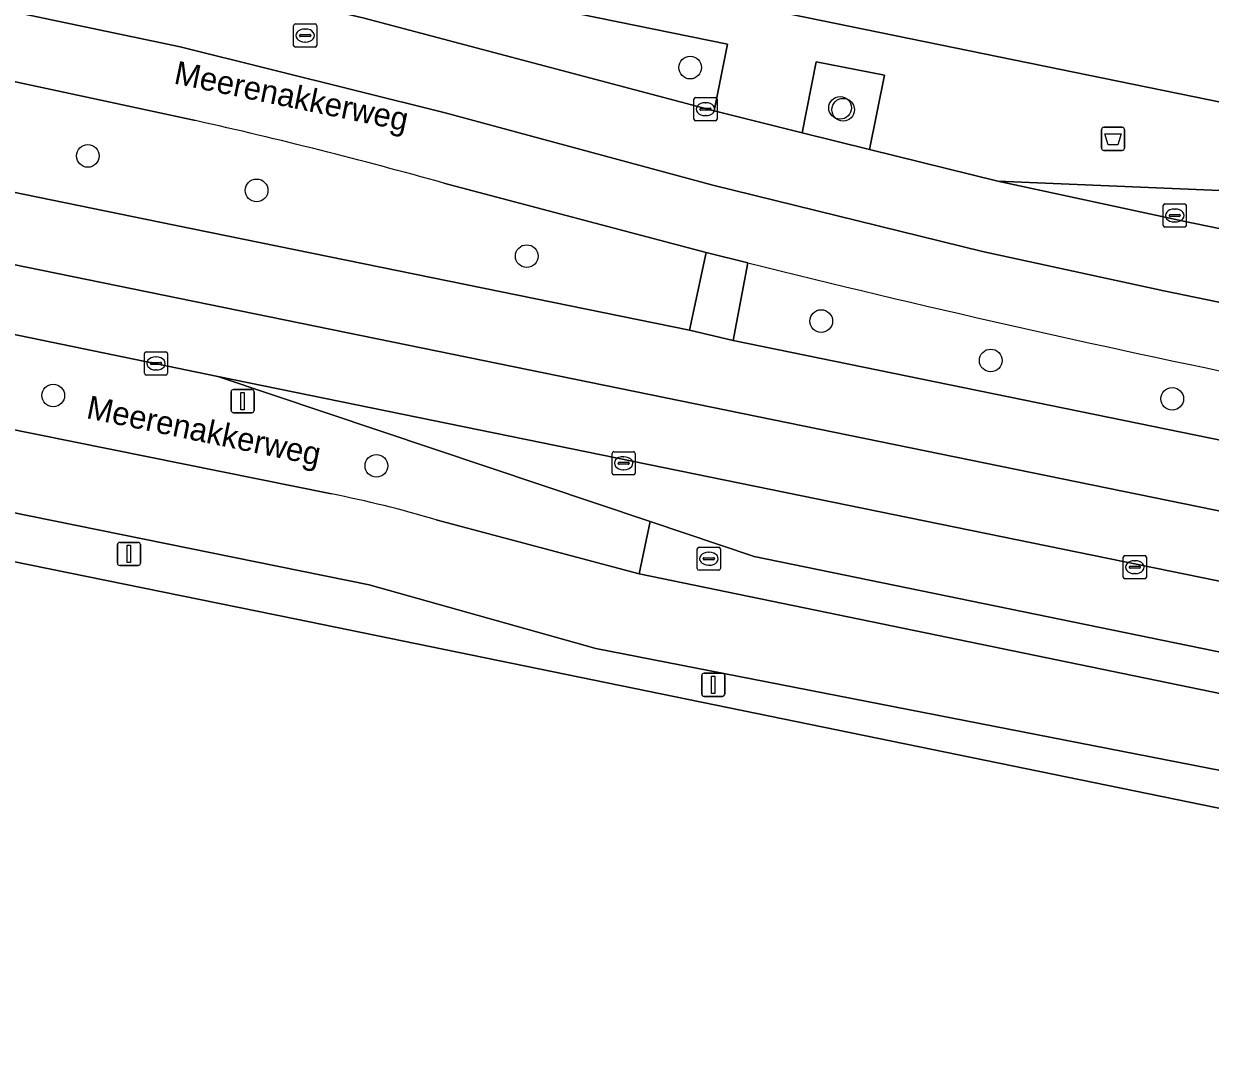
# Model space of a CAD drawing. Extents: x 157692 to 159674, y 381452 to 383291.
# Drawn here: x 158207.7 to 158258.9, y 382136.5 to 382181.5 of the extents above; entities that cross this region are included whole.
import ezdxf

# ---------------------------------------------------------------- set-up
doc = ezdxf.new("R2010")
doc.units = 0
for name, color, linetype in [('IMGEO_Afvalbak', 7, 'Continuous'), ('IMGEO_Berm_groen', 7, 'Continuous'), ('IMGEO_Boom', 7, 'Continuous'), ('IMGEO_Erf', 7, 'Continuous'), ('IMGEO_Fietspad_gesloten', 7, 'Continuous'), ('IMGEO_Kolk', 7, 'Continuous'), ('IMGEO_Lichtmast', 7, 'Continuous'), ('IMGEO_Openbare_ruimte_label', 7, 'Continuous'), ('IMGEO_Rijbaan_lokaal_gesloten', 7, 'Continuous'), ('IMGEO_Rijbaan_regionaal_gesloten', 7, 'Continuous'), ('IMGEO_Rioolput', 7, 'Continuous'), ('IMGEO_Verkeerseiland_groen', 7, 'Continuous'), ('IMGEO_Voetpad_open', 7, 'Continuous')]:
    doc.layers.add(name, color=color, linetype=linetype)

msp = doc.modelspace()

# ---------------------------------------------------------------- linework, layer by layer
at = {"layer": 'IMGEO_Afvalbak'}
for p, q in [((158254.235, 382176.162), (158254.235, 382176.962)), ((158254.235, 382176.962), (158254.235, 382176.162)), ((158254.335, 382177.062), (158255.125, 382177.062)), ((158255.125, 382177.062), (158254.335, 382177.062)), ((158255.225, 382176.962), (158255.225, 382176.162)), ((158255.225, 382176.162), (158255.225, 382176.962)), ((158255.125, 382176.062), (158254.335, 382176.062)), ((158254.335, 382176.062), (158255.125, 382176.062))]:
    msp.add_line(p, q, dxfattribs=at)
msp.add_lwpolyline([(158254.378, 382176.776), (158255.082, 382176.776), (158254.933, 382176.306), (158254.527, 382176.306), (158254.378, 382176.776)], dxfattribs=at)
for centre, start, end in [((158254.335, 382176.962), 90, 180), ((158254.335, 382176.962), 90, 180), ((158255.125, 382176.962), 0, 90), ((158255.125, 382176.962), 360, 90), ((158254.335, 382176.162), 180, 270), ((158254.335, 382176.162), 180, 270), ((158255.125, 382176.162), 270, 0), ((158255.125, 382176.162), 270, 0)]:
    msp.add_arc(centre, 0.1, start, end, dxfattribs=at)
at = {"layer": 'IMGEO_Berm_groen'}
msp.add_lwpolyline([(158217.378, 382184.889), (158216.981, 382183.063), (158222.394, 382181.778), (158237.511, 382177.767), (158238.086, 382180.651)], close=True, dxfattribs=at)
for points in [[(158215.125, 382177.352), (158206.323, 382179.235), (158205.35, 382174.654), (158214.208, 382172.83), (158236.448, 382168.3), (158237.16, 382171.658), (158225.845, 382174.652)], [(158238.963, 382171.216), (158238.332, 382167.86), (158332.654, 382148.555), (158337.281, 382147.627)], [(158216.08, 382166.299), (158204.843, 382168.616), (158202.239, 382166.987), (158201.858, 382165.089), (158220.985, 382161.23)], [(158225.504, 382160.111), (158234.272, 382157.776), (158234.755, 382160.038), (158216.08, 382166.299)]]:
    msp.add_lwpolyline(points, dxfattribs=at)
for centre, radius, start, end in [((158168.564, 381969.857), 212.654, 74.37377, 77.35262), ((158363, 382666.095), 510.187, 255.92925, 258.52743), ((158211.851, 382114.657), 47.46, 73.2808, 78.9034)]:
    msp.add_arc(centre, radius, start, end, dxfattribs=at)
at = {"layer": 'IMGEO_Boom'}
for centre in [(158236.473, 382179.64), (158242.947, 382177.899), (158243.08, 382177.822), (158210.471, 382175.825), (158217.757, 382174.339), (158229.417, 382171.5), (158242.135, 382168.695), (158249.451, 382166.995), (158208.977, 382165.478), (158257.29, 382165.334), (158222.926, 382162.444)]:
    msp.add_circle(centre, 0.489, dxfattribs=at)
at = {"layer": 'IMGEO_Erf'}
for points in [[(158244.45, 382340.754), (158240.4, 382321.2), (158235.573, 382297.761), (158234.161, 382290.853), (158229.78, 382269.461), (158225.787, 382250), (158225.725, 382249.696), (158216.641, 382204.803), (158214.109, 382192.305), (158213.748, 382190.526), (158214.442, 382188.118), (158215.74, 382187.088), (158329.552, 382163.801), (158340.615, 382161.542)], [(158482.902, 382100.939), (158451.557, 382108.262), (158420.864, 382114.543), (158420.794, 382114.557), (158413.202, 382116.111), (158407.519, 382117.274), (158341.43, 382130.834), (158335.43, 382132.061), (158334.656, 382132.219), (158219.414, 382155.844), (158206.316, 382158.502)]]:
    msp.add_lwpolyline(points, dxfattribs=at)
at = {"layer": 'IMGEO_Fietspad_gesloten'}
for points in [[(158220.985, 382161.23), (158201.858, 382165.089), (158188.611, 382167.78), (158162.259, 382173.124)], [(158159.005, 382170.201), (158187.438, 382164.416), (158201.188, 382161.648), (158222.611, 382157.3), (158232.397, 382154.551), (158296.287, 382142.071), (158300.227, 382141.376), (158311.012, 382139.189), (158315.925, 382138.175), (158316.6, 382141.413)], [(158316.6, 382141.413), (158316.605, 382141.634), (158311.936, 382142.594), (158297.48, 382145.479), (158277.512, 382148.874), (158234.272, 382157.776), (158225.504, 382160.111)]]:
    msp.add_lwpolyline(points, dxfattribs=at)
msp.add_arc((158211.851, 382114.657), 47.46, 73.2808, 78.9034, dxfattribs=at)
at = {"layer": 'IMGEO_Kolk'}
for p, q in [((158236.637, 382177.418), (158236.637, 382178.27)), ((158236.712, 382178.344), (158237.564, 382178.344)), ((158237.125, 382178.124), (158237.15, 382178.124)), ((158237.638, 382178.27), (158237.638, 382177.418)), ((158236.896, 382177.838), (158236.896, 382177.85)), ((158237.334, 382177.801), (158236.936, 382177.801)), ((158236.939, 382177.887), (158237.337, 382177.887)), ((158237.38, 382177.85), (158237.38, 382177.838)), ((158237.564, 382177.344), (158236.712, 382177.344)), ((158237.148, 382177.564), (158237.123, 382177.564)), ((158256.896, 382172.827), (158256.896, 382173.679)), ((158256.971, 382173.753), (158257.823, 382173.753)), ((158257.384, 382173.533), (158257.409, 382173.533)), ((158257.897, 382173.679), (158257.897, 382172.827)), ((158257.155, 382173.247), (158257.155, 382173.259)), ((158257.593, 382173.21), (158257.195, 382173.21)), ((158257.198, 382173.296), (158257.596, 382173.296)), ((158257.639, 382173.259), (158257.639, 382173.247)), ((158257.823, 382172.753), (158256.971, 382172.753)), ((158257.407, 382172.973), (158257.382, 382172.973)), ((158212.987, 382167.365), (158213.839, 382167.365)), ((158212.912, 382166.439), (158212.912, 382167.291)), ((158213.171, 382166.859), (158213.171, 382166.871)), ((158213.214, 382166.908), (158213.612, 382166.908)), ((158213.4, 382167.145), (158213.425, 382167.145)), ((158213.655, 382166.871), (158213.655, 382166.859)), ((158213.913, 382167.291), (158213.913, 382166.439)), ((158213.839, 382166.365), (158212.987, 382166.365)), ((158213.609, 382166.822), (158213.211, 382166.822)), ((158213.423, 382166.585), (158213.398, 382166.585)), ((158233.104, 382162.129), (158233.104, 382162.981)), ((158233.179, 382163.055), (158234.031, 382163.055)), ((158233.592, 382162.835), (158233.617, 382162.835)), ((158234.105, 382162.981), (158234.105, 382162.129)), ((158233.363, 382162.549), (158233.363, 382162.561)), ((158233.801, 382162.512), (158233.403, 382162.512)), ((158233.406, 382162.598), (158233.804, 382162.598)), ((158233.615, 382162.275), (158233.59, 382162.275)), ((158233.847, 382162.561), (158233.847, 382162.549)), ((158234.031, 382162.055), (158233.179, 382162.055)), ((158255.174, 382157.642), (158255.174, 382158.494)), ((158255.249, 382158.568), (158256.101, 382158.568)), ((158255.662, 382158.348), (158255.687, 382158.348)), ((158256.175, 382158.494), (158256.175, 382157.642)), ((158255.433, 382158.062), (158255.433, 382158.074)), ((158255.871, 382158.025), (158255.473, 382158.025)), ((158255.476, 382158.111), (158255.874, 382158.111)), ((158255.685, 382157.788), (158255.66, 382157.788)), ((158255.917, 382158.074), (158255.917, 382158.062)), ((158256.101, 382157.568), (158255.249, 382157.568))]:
    msp.add_line(p, q, dxfattribs=at)
for points in [[(158236.637, 382177.418), (158236.637, 382178.27)], [(158236.712, 382178.344), (158237.564, 382178.344)], [(158237.638, 382178.27), (158237.638, 382177.418)], [(158237.564, 382177.344), (158236.712, 382177.344)], [(158256.896, 382172.827), (158256.896, 382173.679)], [(158256.971, 382173.753), (158257.823, 382173.753)], [(158257.897, 382173.679), (158257.897, 382172.827)], [(158257.823, 382172.753), (158256.971, 382172.753)], [(158212.987, 382167.365), (158213.839, 382167.365)], [(158212.912, 382166.439), (158212.912, 382167.291)], [(158213.913, 382167.291), (158213.913, 382166.439)], [(158213.839, 382166.365), (158212.987, 382166.365)], [(158233.104, 382162.129), (158233.104, 382162.981)], [(158233.179, 382163.055), (158234.031, 382163.055)], [(158234.105, 382162.981), (158234.105, 382162.129)], [(158234.031, 382162.055), (158233.179, 382162.055)], [(158255.174, 382157.642), (158255.174, 382158.494)], [(158255.249, 382158.568), (158256.101, 382158.568)], [(158256.175, 382158.494), (158256.175, 382157.642)], [(158256.101, 382157.568), (158255.249, 382157.568)]]:
    msp.add_lwpolyline(points, dxfattribs=at)
for centre, radius, start, end in [((158236.714, 382178.268), 0.0765, 91.552, 178.448), ((158236.714, 382178.268), 0.0765, 91.552, 178.448), ((158237.562, 382178.268), 0.0765, 1.552, 88.448), ((158237.562, 382178.268), 0.0765, 1.552, 88.448), ((158236.936, 382177.847), 0.0403, 85.8775, 175.7526), ((158236.933, 382177.837), 0.0366, 178.938, 274.7102), ((158237.337, 382177.844), 0.043, 264.8664, 352.4533), ((158237.341, 382177.849), 0.0386, 1.7309, 96.639), ((158236.714, 382177.42), 0.0765, 181.552, 268.448), ((158236.714, 382177.42), 0.0765, 181.552, 268.448), ((158237.562, 382177.42), 0.0765, 271.552, 358.448), ((158237.562, 382177.42), 0.0765, 271.552, 358.448), ((158256.973, 382173.677), 0.0765, 91.552, 178.448), ((158256.973, 382173.677), 0.0765, 91.552, 178.448), ((158257.821, 382173.677), 0.0765, 1.552, 88.448), ((158257.821, 382173.677), 0.0765, 1.552, 88.448), ((158257.195, 382173.256), 0.0403, 85.8775, 175.7526), ((158257.192, 382173.246), 0.0366, 178.938, 274.7102), ((158257.596, 382173.253), 0.043, 264.8664, 352.4533), ((158257.6, 382173.258), 0.0386, 1.7309, 96.639), ((158256.973, 382172.829), 0.0765, 181.552, 268.448), ((158256.973, 382172.829), 0.0765, 181.552, 268.448), ((158257.821, 382172.829), 0.0765, 271.552, 358.448), ((158257.821, 382172.829), 0.0765, 271.552, 358.448), ((158212.989, 382167.289), 0.0765, 91.552, 178.448), ((158212.989, 382167.289), 0.0765, 91.552, 178.448), ((158213.837, 382167.289), 0.0765, 1.552, 88.448), ((158213.837, 382167.289), 0.0765, 1.552, 88.448), ((158213.211, 382166.868), 0.0403, 85.8775, 175.7526), ((158213.208, 382166.858), 0.0366, 178.938, 274.7102), ((158213.612, 382166.865), 0.043, 264.8664, 352.4533), ((158213.616, 382166.87), 0.0386, 1.7309, 96.639), ((158212.989, 382166.441), 0.0765, 181.552, 268.448), ((158212.989, 382166.441), 0.0765, 181.552, 268.448), ((158213.837, 382166.441), 0.0765, 271.552, 358.448), ((158213.837, 382166.441), 0.0765, 271.552, 358.448), ((158233.181, 382162.979), 0.0765, 91.552, 178.448), ((158233.181, 382162.979), 0.0765, 91.552, 178.448), ((158234.029, 382162.979), 0.0765, 1.552, 88.448), ((158234.029, 382162.979), 0.0765, 1.552, 88.448), ((158233.403, 382162.558), 0.0403, 85.8775, 175.7526), ((158233.4, 382162.548), 0.0366, 178.938, 274.7102), ((158233.804, 382162.555), 0.043, 264.8664, 352.4533), ((158233.808, 382162.56), 0.0386, 1.7309, 96.639), ((158233.181, 382162.131), 0.0765, 181.552, 268.448), ((158233.181, 382162.131), 0.0765, 181.552, 268.448), ((158234.029, 382162.131), 0.0765, 271.552, 358.448), ((158234.029, 382162.131), 0.0765, 271.552, 358.448), ((158255.251, 382158.492), 0.0765, 91.552, 178.448), ((158255.251, 382158.492), 0.0765, 91.552, 178.448), ((158256.099, 382158.492), 0.0765, 1.552, 88.448), ((158256.099, 382158.492), 0.0765, 1.552, 88.448), ((158255.251, 382157.644), 0.0765, 181.552, 268.448), ((158255.251, 382157.644), 0.0765, 181.552, 268.448), ((158255.473, 382158.071), 0.0403, 85.8775, 175.7526), ((158255.47, 382158.061), 0.0366, 178.938, 274.7102), ((158255.874, 382158.068), 0.043, 264.8664, 352.4533), ((158255.878, 382158.073), 0.0386, 1.7309, 96.639), ((158256.099, 382157.644), 0.0765, 271.552, 358.448), ((158256.099, 382157.644), 0.0765, 271.552, 358.448)]:
    msp.add_arc(centre, radius, start, end, dxfattribs=at)
for centre, major_axis, ratio, start_param, end_param in [((158237.124, 382177.844), (-0.387, 0.002), 0.722429, 4.712389, 7.853982), ((158237.149, 382177.844), (-0.39, 0.002), 0.717154, 1.570796, 4.712389), ((158257.383, 382173.253), (-0.387, 0.002), 0.722429, 4.712389, 7.853982), ((158257.408, 382173.253), (-0.39, 0.002), 0.717154, 1.570796, 4.712389), ((158213.399, 382166.865), (-0.387, 0.002), 0.722429, 4.712389, 7.853982), ((158213.424, 382166.865), (-0.39, 0.002), 0.717154, 1.570796, 4.712389), ((158233.591, 382162.555), (-0.387, 0.002), 0.722429, 4.712389, 7.853982), ((158233.616, 382162.555), (-0.39, 0.002), 0.717154, 1.570796, 4.712389), ((158255.661, 382158.068), (-0.387, 0.002), 0.722429, 4.712389, 7.853982), ((158255.686, 382158.068), (-0.39, 0.002), 0.717154, 1.570796, 4.712389)]:
    msp.add_ellipse(centre, major_axis=major_axis, ratio=ratio, start_param=start_param, end_param=end_param, dxfattribs=at)
at = {"layer": 'IMGEO_Lichtmast'}
for p, q in [((158216.656, 382164.839), (158216.656, 382165.639)), ((158216.656, 382165.639), (158216.656, 382164.839)), ((158216.756, 382165.739), (158217.546, 382165.739)), ((158217.546, 382165.739), (158216.756, 382165.739)), ((158217.646, 382165.639), (158217.646, 382164.839)), ((158217.646, 382164.839), (158217.646, 382165.639)), ((158217.546, 382164.739), (158216.756, 382164.739)), ((158216.756, 382164.739), (158217.546, 382164.739)), ((158211.748, 382158.24), (158211.748, 382159.04)), ((158211.748, 382159.04), (158211.748, 382158.24)), ((158211.848, 382159.14), (158212.638, 382159.14)), ((158212.638, 382159.14), (158211.848, 382159.14)), ((158212.738, 382159.04), (158212.738, 382158.24)), ((158212.738, 382158.24), (158212.738, 382159.04)), ((158212.638, 382158.14), (158211.848, 382158.14)), ((158211.848, 382158.14), (158212.638, 382158.14)), ((158236.975, 382152.59), (158236.975, 382153.39)), ((158236.975, 382153.39), (158236.975, 382152.59)), ((158237.075, 382153.49), (158237.865, 382153.49)), ((158237.865, 382153.49), (158237.075, 382153.49)), ((158237.965, 382153.39), (158237.965, 382152.59)), ((158237.965, 382152.59), (158237.965, 382153.39)), ((158237.865, 382152.49), (158237.075, 382152.49)), ((158237.075, 382152.49), (158237.865, 382152.49))]:
    msp.add_line(p, q, dxfattribs=at)
for points in [[(158217.076, 382165.614), (158217.226, 382165.614), (158217.226, 382164.864), (158217.076, 382164.864), (158217.076, 382165.614)], [(158212.168, 382159.015), (158212.318, 382159.015), (158212.318, 382158.265), (158212.168, 382158.265), (158212.168, 382159.015)], [(158237.395, 382153.365), (158237.545, 382153.365), (158237.545, 382152.615), (158237.395, 382152.615), (158237.395, 382153.365)]]:
    msp.add_lwpolyline(points, dxfattribs=at)
for centre, start, end in [((158216.756, 382165.639), 90, 180), ((158216.756, 382165.639), 90, 180), ((158217.546, 382165.639), 0, 90), ((158217.546, 382165.639), 360, 90), ((158216.756, 382164.839), 180, 270), ((158216.756, 382164.839), 180, 270), ((158217.546, 382164.839), 270, 0), ((158217.546, 382164.839), 270, 0), ((158211.848, 382159.04), 90, 180), ((158211.848, 382159.04), 90, 180), ((158212.638, 382159.04), 0, 90), ((158212.638, 382159.04), 360, 90), ((158211.848, 382158.24), 180, 270), ((158211.848, 382158.24), 180, 270), ((158212.638, 382158.24), 270, 0), ((158212.638, 382158.24), 270, 0), ((158237.075, 382153.39), 90, 180), ((158237.075, 382153.39), 90, 180), ((158237.865, 382153.39), 0, 90), ((158237.865, 382153.39), 360, 90), ((158237.075, 382152.59), 180, 270), ((158237.075, 382152.59), 180, 270), ((158237.865, 382152.59), 270, 0), ((158237.865, 382152.59), 270, 0)]:
    msp.add_arc(centre, 0.1, start, end, dxfattribs=at)
at = {"layer": 'IMGEO_Rijbaan_lokaal_gesloten'}
for points in [[(158312.633, 382161.717), (158311.966, 382161.947), (158306.509, 382163.787), (158295.909, 382167.348), (158289.33, 382169.533), (158267.837, 382173.953), (158267.219, 382174.004), (158249.756, 382174.73), (158257.777, 382173.009)], [(158234.755, 382160.038), (158239.245, 382158.524), (158260.766, 382154.11), (158278.412, 382153.569), (158216.08, 382166.299)]]:
    msp.add_lwpolyline(points, close=True, dxfattribs=at)
at = {"layer": 'IMGEO_Rijbaan_regionaal_gesloten'}
for points in [[(158261.524, 382166.102), (158275.322, 382163.2), (158286.197, 382161.062), (158295.36, 382159.103), (158314.777, 382155.136), (158321.46, 382153.803), (158323.945, 382153.28), (158334.226, 382151.239), (158339.086, 382150.367), (158341.105, 382150.035), (158343.515, 382152.527), (158327.525, 382155.488), (158318.888, 382157.281), (158300.095, 382161.181), (158268.722, 382167.572), (158256.931, 382169.996), (158249.098, 382171.701), (158237.46, 382174.557), (158225.893, 382177.689), (158214.463, 382180.529), (158188.034, 382186.098), (157930.794, 382238.814)], [(158170.92, 382175.562), (158187.319, 382172.195), (158204.843, 382168.616), (158216.08, 382166.299), (158278.412, 382153.569), (158333.614, 382142.258), (158336.056, 382144.815), (158206.473, 382171.3), (158031.467, 382207.214), (158024.234, 382208.503), (158020.135, 382209.234), (158016.646, 382209.742), (158012.613, 382210.388), (158008.566, 382210.941), (157996.273, 382212.623), (157992.778, 382213.101), (157988.349, 382213.708), (157984.656, 382214.298), (157972.663, 382216.316), (157960.705, 382218.534), (157952.268, 382220.278), (157944.252, 382221.934), (157933.19, 382224.57), (157925.243, 382226.645)], [(158012.828, 382218.933), (158142.514, 382192.31), (158170.978, 382186.516), (158185.711, 382183.483), (158196.081, 382181.334), (158199.217, 382180.702), (158203.207, 382179.878), (158206.323, 382179.235), (158215.125, 382177.352)], [(158188.034, 382186.098), (158214.463, 382180.529), (158225.893, 382177.689), (158237.46, 382174.557), (158249.098, 382171.701), (158256.931, 382169.996), (158268.722, 382167.572), (158300.095, 382161.181), (158318.888, 382157.281), (158327.525, 382155.488), (158343.515, 382152.527), (158346.089, 382155.189), (158341.57, 382155.982), (158334.739, 382157.23), (158325.962, 382159.007), (158312.633, 382161.717), (158257.777, 382173.009), (158249.756, 382174.73), (158244.222, 382176.102), (158241.316, 382176.823), (158237.511, 382177.767), (158222.394, 382181.778), (158216.981, 382183.063), (158188.223, 382189.088)], [(158206.473, 382171.3), (158336.056, 382144.815), (158338.533, 382147.375), (158337.281, 382147.627), (158332.654, 382148.555), (158238.332, 382167.86), (158236.448, 382168.3), (158214.208, 382172.83), (158205.35, 382174.654)], [(158225.845, 382174.652), (158237.16, 382171.658), (158238.963, 382171.216)]]:
    msp.add_lwpolyline(points, dxfattribs=at)
for centre, radius, start, end in [((158168.564, 381969.857), 212.654, 74.37377, 77.35262), ((158363, 382666.095), 510.187, 255.92925, 258.52743)]:
    msp.add_arc(centre, radius, start, end, dxfattribs=at)
at = {"layer": 'IMGEO_Rioolput'}
for p, q in [((158219.355, 382180.597), (158219.355, 382181.449)), ((158219.43, 382181.523), (158220.282, 382181.523)), ((158219.843, 382181.303), (158219.868, 382181.303)), ((158220.356, 382181.449), (158220.356, 382180.597)), ((158219.614, 382181.017), (158219.614, 382181.029)), ((158220.052, 382180.98), (158219.654, 382180.98)), ((158219.657, 382181.066), (158220.055, 382181.066)), ((158219.866, 382180.743), (158219.841, 382180.743)), ((158220.098, 382181.029), (158220.098, 382181.017)), ((158220.282, 382180.523), (158219.43, 382180.523)), ((158236.784, 382158.006), (158236.784, 382158.858)), ((158236.859, 382158.932), (158237.711, 382158.932)), ((158237.272, 382158.712), (158237.297, 382158.712)), ((158237.785, 382158.858), (158237.785, 382158.006)), ((158237.043, 382158.426), (158237.043, 382158.438)), ((158237.481, 382158.389), (158237.083, 382158.389)), ((158237.086, 382158.475), (158237.484, 382158.475)), ((158237.295, 382158.152), (158237.27, 382158.152)), ((158237.527, 382158.438), (158237.527, 382158.426)), ((158237.711, 382157.932), (158236.859, 382157.932))]:
    msp.add_line(p, q, dxfattribs=at)
for points in [[(158219.355, 382180.597), (158219.355, 382181.449)], [(158219.43, 382181.523), (158220.282, 382181.523)], [(158220.356, 382181.449), (158220.356, 382180.597)], [(158220.282, 382180.523), (158219.43, 382180.523)], [(158236.784, 382158.006), (158236.784, 382158.858)], [(158236.859, 382158.932), (158237.711, 382158.932)], [(158237.785, 382158.858), (158237.785, 382158.006)], [(158237.711, 382157.932), (158236.859, 382157.932)]]:
    msp.add_lwpolyline(points, dxfattribs=at)
for centre, radius, start, end in [((158219.432, 382181.447), 0.0765, 91.552, 178.448), ((158219.432, 382181.447), 0.0765, 91.552, 178.448), ((158220.28, 382181.447), 0.0765, 1.552, 88.448), ((158220.28, 382181.447), 0.0765, 1.552, 88.448), ((158219.654, 382181.026), 0.0403, 85.8775, 175.7526), ((158219.651, 382181.016), 0.0366, 178.938, 274.7102), ((158220.055, 382181.023), 0.043, 264.8664, 352.4533), ((158220.059, 382181.028), 0.0386, 1.7309, 96.639), ((158219.432, 382180.599), 0.0765, 181.552, 268.448), ((158219.432, 382180.599), 0.0765, 181.552, 268.448), ((158220.28, 382180.599), 0.0765, 271.552, 358.448), ((158220.28, 382180.599), 0.0765, 271.552, 358.448), ((158236.861, 382158.856), 0.0765, 91.552, 178.448), ((158236.861, 382158.856), 0.0765, 91.552, 178.448), ((158237.709, 382158.856), 0.0765, 1.552, 88.448), ((158237.709, 382158.856), 0.0765, 1.552, 88.448), ((158237.083, 382158.435), 0.0403, 85.8775, 175.7526), ((158237.08, 382158.425), 0.0366, 178.938, 274.7102), ((158237.484, 382158.432), 0.043, 264.8664, 352.4533), ((158237.488, 382158.437), 0.0386, 1.7309, 96.639), ((158236.861, 382158.008), 0.0765, 181.552, 268.448), ((158236.861, 382158.008), 0.0765, 181.552, 268.448), ((158237.709, 382158.008), 0.0765, 271.552, 358.448), ((158237.709, 382158.008), 0.0765, 271.552, 358.448)]:
    msp.add_arc(centre, radius, start, end, dxfattribs=at)
for centre, major_axis, ratio, start_param, end_param in [((158219.842, 382181.023), (-0.387, 0.002), 0.722429, 4.712389, 7.853982), ((158219.867, 382181.023), (-0.39, 0.002), 0.717154, 1.570796, 4.712389), ((158237.271, 382158.432), (-0.387, 0.002), 0.722429, 4.712389, 7.853982), ((158237.296, 382158.432), (-0.39, 0.002), 0.717154, 1.570796, 4.712389)]:
    msp.add_ellipse(centre, major_axis=major_axis, ratio=ratio, start_param=start_param, end_param=end_param, dxfattribs=at)
at = {"layer": 'IMGEO_Verkeerseiland_groen'}
msp.add_lwpolyline([(158244.859, 382179.316), (158241.909, 382179.893), (158241.316, 382176.823), (158244.222, 382176.102)], close=True, dxfattribs=at)
at = {"layer": 'IMGEO_Voetpad_open'}
for points in [[(158216.981, 382183.063), (158217.378, 382184.889), (158238.086, 382180.651), (158237.511, 382177.767), (158241.316, 382176.823), (158241.909, 382179.893), (158244.859, 382179.316), (158244.222, 382176.102), (158249.756, 382174.73), (158267.219, 382174.004), (158267.837, 382173.953), (158289.33, 382169.533), (158289.45, 382170.147), (158296.902, 382168.638), (158305.074, 382166.969), (158328.36, 382162.202), (158329.552, 382163.801), (158215.74, 382187.088)], [(158232.397, 382154.551), (158222.611, 382157.3), (158201.188, 382161.648), (158200.819, 382159.771), (158201.692, 382159.577), (158201.667, 382159.445), (158205.717, 382158.623), (158206.19, 382158.527), (158206.316, 382158.502), (158219.414, 382155.844), (158334.656, 382132.219), (158335.43, 382132.061), (158341.43, 382130.834), (158407.519, 382117.274), (158413.202, 382116.111), (158413.639, 382118.174), (158363.947, 382128.382), (158355.402, 382130.125), (158355.15, 382130.186), (158348.218, 382131.053)], [(158319.862, 382137.363), (158315.925, 382138.175), (158311.012, 382139.189), (158300.227, 382141.376), (158296.287, 382142.071), (158232.397, 382154.551)]]:
    msp.add_lwpolyline(points, dxfattribs=at)
for points in [[(158237.16, 382171.658), (158236.448, 382168.3), (158238.332, 382167.86), (158238.963, 382171.216)], [(158234.272, 382157.776), (158277.512, 382148.874), (158278.412, 382153.569), (158260.766, 382154.11), (158239.245, 382158.524), (158234.755, 382160.038)]]:
    msp.add_lwpolyline(points, close=True, dxfattribs=at)

# ---------------------------------------------------------------- texts
at = {"layer": 'IMGEO_Openbare_ruimte_label'}
for p in [(158214.144, 382178.958), (158210.364, 382164.512)]:
    msp.add_text('Meerenakkerweg', height=1, rotation=348.3416, dxfattribs=at).set_placement(p)

doc.saveas('drawing.dxf')
